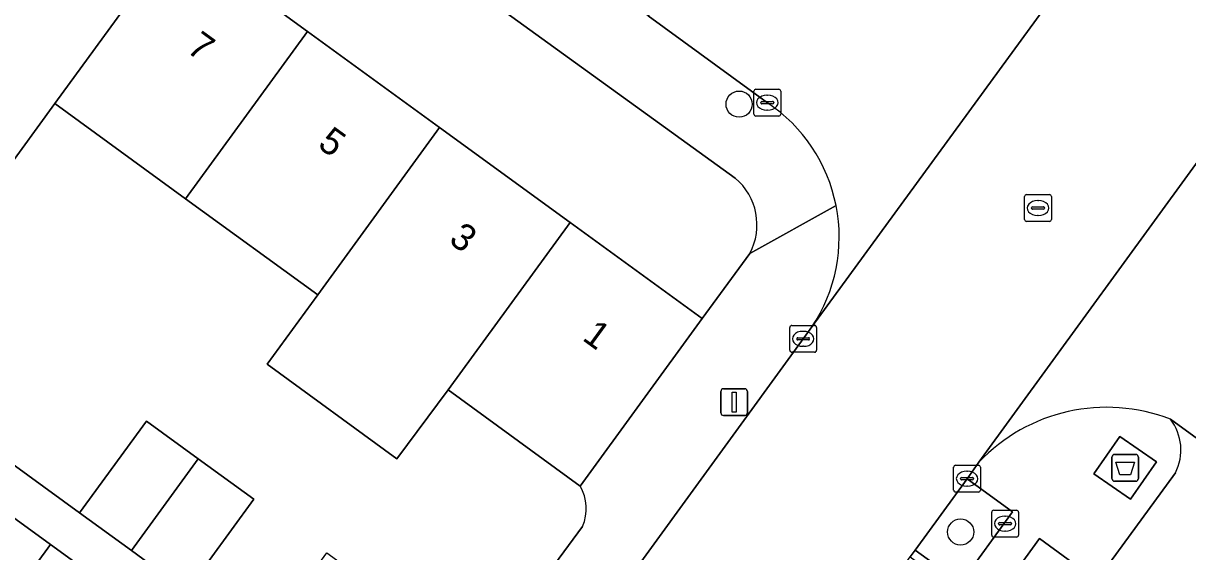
# Model space of a CAD drawing. Extents: x 159674 to 160531, y 382172 to 382904.
# Drawn here: x 160250.27 to 160293.73, y 382582.22 to 382601.94 of the extents above; entities that cross this region are included whole.
import ezdxf

# ---------------------------------------------------------------- set-up
doc = ezdxf.new("R2010")
doc.units = 0
for name, color, linetype in [('IMGEO_Afval_apart_plaats', 7, 'Continuous'), ('IMGEO_Boom', 7, 'Continuous'), ('IMGEO_Brandkraan', 7, 'Continuous'), ('IMGEO_Erf', 7, 'Continuous'), ('IMGEO_Groenvoorziening', 7, 'Continuous'), ('IMGEO_Kolk', 7, 'Continuous'), ('IMGEO_Lichtmast', 7, 'Continuous'), ('IMGEO_Muur', 7, 'Continuous'), ('IMGEO_Pand', 7, 'Continuous'), ('IMGEO_Pand_nummerreeks', 7, 'Continuous'), ('IMGEO_Parkeervlak_open', 7, 'Continuous'), ('IMGEO_Rijbaan_lokaal_gesloten', 7, 'Continuous'), ('IMGEO_Rijbaan_lokaal_open', 7, 'Continuous'), ('IMGEO_Rioolput', 7, 'Continuous'), ('IMGEO_Voetpad_gesloten', 7, 'Continuous'), ('IMGEO_Voetpad_open', 7, 'Continuous')]:
    doc.layers.add(name, color=color, linetype=linetype)

msp = doc.modelspace()

# ---------------------------------------------------------------- linework, layer by layer
at = {"layer": 'IMGEO_Afval_apart_plaats'}
for p, q in [((160290.903, 382584.947), (160290.903, 382585.747)), ((160290.903, 382585.747), (160290.903, 382584.947)), ((160291.003, 382585.847), (160291.793, 382585.847)), ((160291.793, 382585.847), (160291.003, 382585.847)), ((160291.893, 382585.747), (160291.893, 382584.947)), ((160291.893, 382584.947), (160291.893, 382585.747)), ((160291.793, 382584.847), (160291.003, 382584.847)), ((160291.003, 382584.847), (160291.793, 382584.847))]:
    msp.add_line(p, q, dxfattribs=at)
msp.add_lwpolyline([(160291.046, 382585.561), (160291.75, 382585.561), (160291.601, 382585.091), (160291.195, 382585.091), (160291.046, 382585.561)], dxfattribs=at)
for centre, start, end in [((160291.003, 382585.747), 90, 180), ((160291.003, 382585.747), 90, 180), ((160291.793, 382585.747), 0, 90), ((160291.793, 382585.747), 360, 90), ((160291.003, 382584.947), 180, 270), ((160291.003, 382584.947), 180, 270), ((160291.793, 382584.947), 270, 0), ((160291.793, 382584.947), 270, 0)]:
    msp.add_arc(centre, 0.1, start, end, dxfattribs=at)
at = {"layer": 'IMGEO_Boom'}
for centre in [(160276.99, 382598.923), (160285.257, 382582.952)]:
    msp.add_circle(centre, 0.489, dxfattribs=at)
at = {"layer": 'IMGEO_Brandkraan'}
for p, q in [((160286.416, 382582.839), (160286.416, 382583.691)), ((160286.491, 382583.765), (160287.343, 382583.765)), ((160286.904, 382583.545), (160286.929, 382583.545)), ((160287.417, 382583.691), (160287.417, 382582.839)), ((160286.675, 382583.259), (160286.675, 382583.271)), ((160287.113, 382583.222), (160286.715, 382583.222)), ((160286.718, 382583.308), (160287.116, 382583.308)), ((160287.159, 382583.271), (160287.159, 382583.259)), ((160287.343, 382582.765), (160286.491, 382582.765)), ((160286.927, 382582.985), (160286.902, 382582.985))]:
    msp.add_line(p, q, dxfattribs=at)
for points in [[(160286.416, 382582.839), (160286.416, 382583.691)], [(160286.491, 382583.765), (160287.343, 382583.765)], [(160287.417, 382583.691), (160287.417, 382582.839)], [(160287.343, 382582.765), (160286.491, 382582.765)]]:
    msp.add_lwpolyline(points, dxfattribs=at)
for centre, radius, start, end in [((160286.493, 382583.689), 0.0765, 91.552, 178.448), ((160286.493, 382583.689), 0.0765, 91.552, 178.448), ((160287.341, 382583.689), 0.0765, 1.552, 88.448), ((160287.341, 382583.689), 0.0765, 1.552, 88.448), ((160286.715, 382583.268), 0.0403, 85.8775, 175.7526), ((160286.712, 382583.258), 0.0366, 178.938, 274.7102), ((160287.116, 382583.265), 0.043, 264.8664, 352.4533), ((160287.12, 382583.27), 0.0386, 1.7309, 96.639), ((160286.493, 382582.841), 0.0765, 181.552, 268.448), ((160286.493, 382582.841), 0.0765, 181.552, 268.448), ((160287.341, 382582.841), 0.0765, 271.552, 358.448), ((160287.341, 382582.841), 0.0765, 271.552, 358.448)]:
    msp.add_arc(centre, radius, start, end, dxfattribs=at)
for centre, major_axis, ratio, start_param, end_param in [((160286.903, 382583.265), (-0.387, 0.002), 0.722429, 4.712389, 7.853982), ((160286.928, 382583.265), (-0.39, 0.002), 0.717154, 1.570796, 4.712389)]:
    msp.add_ellipse(centre, major_axis=major_axis, ratio=ratio, start_param=start_param, end_param=end_param, dxfattribs=at)
at = {"layer": 'IMGEO_Erf'}
for points in [[(160276.843, 382596.162), (160253.992, 382612.685), (160251.138, 382608.735), (160256.003, 382605.192), (160260.883, 382601.639), (160265.812, 382598.05), (160270.68, 382594.506), (160275.606, 382590.919), (160277.39, 382593.349)], [(160259.378, 382589.214), (160261.261, 382591.801), (160256.332, 382595.389), (160251.452, 382598.943), (160249.571, 382596.36), (160244.707, 382599.903), (160239.649, 382592.926), (160242.566, 382590.809), (160245.059, 382594.233), (160246.995, 382592.823), (160249.066, 382591.315), (160246.573, 382587.891), (160252.375, 382583.666), (160254.868, 382587.09), (160256.804, 382585.68), (160258.875, 382584.172), (160256.382, 382580.748), (160259.119, 382578.762), (160261.605, 382582.176), (160266.618, 382578.526), (160267.346, 382578.004), (160271.149, 382583.159)], [(160248.843, 382579.132), (160251.284, 382582.484), (160245.602, 382586.613), (160243.161, 382583.261), (160241.166, 382584.714), (160239.162, 382586.173), (160241.603, 382589.525), (160238.707, 382591.628), (160234.032, 382585.187), (160239.007, 382581.569), (160238.409, 382580.747), (160243.42, 382577.213), (160241.909, 382575.136), (160246.549, 382571.761), (160246.751, 382571.614), (160248.457, 382573.961), (160253.249, 382570.477), (160251.542, 382568.129), (160256.431, 382564.573)], [(160271.056, 382584.669), (160266.13, 382588.256), (160264.22, 382585.689), (160259.378, 382589.214)]]:
    msp.add_lwpolyline(points, dxfattribs=at)
for centre, radius, start, end in [((160275.386, 382594.419), 2.271, 331.8954, 50.1128), ((160269.604, 382583.822), 1.681, 336.7775, 30.2712)]:
    msp.add_arc(centre, radius, start, end, dxfattribs=at)
at = {"layer": 'IMGEO_Groenvoorziening'}
msp.add_lwpolyline([(160285.497, 382584.942), (160283.56, 382582.27), (160285.262, 382581.037), (160287.198, 382583.709)], close=True, dxfattribs=at)
msp.add_lwpolyline([(160340.442, 382549.369), (160334.331, 382540.968), (160330.288, 382543.909), (160320.097, 382551.321), (160305.863, 382561.673), (160309.033, 382566.031), (160311.974, 382570.074), (160312.894, 382569.405), (160313.791, 382570.579), (160311.658, 382572.109), (160310.584, 382571.385), (160308.218, 382568.127), (160290.343, 382581.143), (160288.198, 382582.705), (160286.206, 382579.962), (160290.265, 382577.019), (160290.699, 382577.618), (160299.084, 382571.539), (160288.827, 382557.394), (160278.496, 382543.145), (160268.164, 382528.897), (160257.833, 382514.648), (160249.448, 382520.727)], dxfattribs=at)
at = {"layer": 'IMGEO_Kolk'}
for p, q in [((160277.542, 382598.552), (160277.542, 382599.404)), ((160277.617, 382599.478), (160278.469, 382599.478)), ((160278.03, 382599.258), (160278.055, 382599.258)), ((160278.543, 382599.404), (160278.543, 382598.552)), ((160277.801, 382598.972), (160277.801, 382598.984)), ((160278.239, 382598.935), (160277.841, 382598.935)), ((160277.844, 382599.021), (160278.242, 382599.021)), ((160278.285, 382598.984), (160278.285, 382598.972)), ((160278.469, 382598.478), (160277.617, 382598.478)), ((160278.053, 382598.698), (160278.028, 382598.698)), ((160278.88, 382589.737), (160278.88, 382590.589)), ((160278.955, 382590.663), (160279.807, 382590.663)), ((160279.881, 382590.589), (160279.881, 382589.737)), ((160279.139, 382590.157), (160279.139, 382590.169)), ((160279.577, 382590.12), (160279.179, 382590.12)), ((160279.182, 382590.206), (160279.58, 382590.206)), ((160279.368, 382590.443), (160279.393, 382590.443)), ((160279.623, 382590.169), (160279.623, 382590.157)), ((160279.807, 382589.663), (160278.955, 382589.663)), ((160279.391, 382589.883), (160279.366, 382589.883)), ((160284.997, 382584.515), (160284.997, 382585.367)), ((160285.072, 382585.441), (160285.924, 382585.441)), ((160285.998, 382585.367), (160285.998, 382584.515)), ((160285.256, 382584.935), (160285.256, 382584.947)), ((160285.694, 382584.898), (160285.296, 382584.898)), ((160285.299, 382584.984), (160285.697, 382584.984)), ((160285.485, 382585.221), (160285.51, 382585.221)), ((160285.74, 382584.947), (160285.74, 382584.935)), ((160285.924, 382584.441), (160285.072, 382584.441)), ((160285.508, 382584.661), (160285.483, 382584.661))]:
    msp.add_line(p, q, dxfattribs=at)
for points in [[(160277.542, 382598.552), (160277.542, 382599.404)], [(160277.617, 382599.478), (160278.469, 382599.478)], [(160278.543, 382599.404), (160278.543, 382598.552)], [(160278.469, 382598.478), (160277.617, 382598.478)], [(160278.88, 382589.737), (160278.88, 382590.589)], [(160278.955, 382590.663), (160279.807, 382590.663)], [(160279.881, 382590.589), (160279.881, 382589.737)], [(160279.807, 382589.663), (160278.955, 382589.663)], [(160284.997, 382584.515), (160284.997, 382585.367)], [(160285.072, 382585.441), (160285.924, 382585.441)], [(160285.998, 382585.367), (160285.998, 382584.515)], [(160285.924, 382584.441), (160285.072, 382584.441)]]:
    msp.add_lwpolyline(points, dxfattribs=at)
for centre, radius, start, end in [((160277.619, 382599.402), 0.0765, 91.552, 178.448), ((160277.619, 382599.402), 0.0765, 91.552, 178.448), ((160278.467, 382599.402), 0.0765, 1.552, 88.448), ((160278.467, 382599.402), 0.0765, 1.552, 88.448), ((160277.841, 382598.981), 0.0403, 85.8775, 175.7526), ((160277.838, 382598.971), 0.0366, 178.938, 274.7102), ((160278.242, 382598.978), 0.043, 264.8664, 352.4533), ((160278.246, 382598.983), 0.0386, 1.7309, 96.639), ((160277.619, 382598.554), 0.0765, 181.552, 268.448), ((160277.619, 382598.554), 0.0765, 181.552, 268.448), ((160278.467, 382598.554), 0.0765, 271.552, 358.448), ((160278.467, 382598.554), 0.0765, 271.552, 358.448), ((160278.957, 382590.587), 0.0765, 91.552, 178.448), ((160278.957, 382590.587), 0.0765, 91.552, 178.448), ((160279.805, 382590.587), 0.0765, 1.552, 88.448), ((160279.805, 382590.587), 0.0765, 1.552, 88.448), ((160279.179, 382590.166), 0.0403, 85.8775, 175.7526), ((160279.176, 382590.156), 0.0366, 178.938, 274.7102), ((160279.58, 382590.163), 0.043, 264.8664, 352.4533), ((160279.584, 382590.168), 0.0386, 1.7309, 96.639), ((160278.957, 382589.739), 0.0765, 181.552, 268.448), ((160278.957, 382589.739), 0.0765, 181.552, 268.448), ((160279.805, 382589.739), 0.0765, 271.552, 358.448), ((160279.805, 382589.739), 0.0765, 271.552, 358.448), ((160285.074, 382585.365), 0.0765, 91.552, 178.448), ((160285.074, 382585.365), 0.0765, 91.552, 178.448), ((160285.922, 382585.365), 0.0765, 1.552, 88.448), ((160285.922, 382585.365), 0.0765, 1.552, 88.448), ((160285.296, 382584.944), 0.0403, 85.8775, 175.7526), ((160285.293, 382584.934), 0.0366, 178.938, 274.7102), ((160285.697, 382584.941), 0.043, 264.8664, 352.4533), ((160285.701, 382584.946), 0.0386, 1.7309, 96.639), ((160285.074, 382584.517), 0.0765, 181.552, 268.448), ((160285.074, 382584.517), 0.0765, 181.552, 268.448), ((160285.922, 382584.517), 0.0765, 271.552, 358.448), ((160285.922, 382584.517), 0.0765, 271.552, 358.448)]:
    msp.add_arc(centre, radius, start, end, dxfattribs=at)
for centre, major_axis, ratio, start_param, end_param in [((160278.029, 382598.978), (-0.387, 0.002), 0.722429, 4.712389, 7.853982), ((160278.054, 382598.978), (-0.39, 0.002), 0.717154, 1.570796, 4.712389), ((160279.367, 382590.163), (-0.387, 0.002), 0.722429, 4.712389, 7.853982), ((160279.392, 382590.163), (-0.39, 0.002), 0.717154, 1.570796, 4.712389), ((160285.484, 382584.941), (-0.387, 0.002), 0.722429, 4.712389, 7.853982), ((160285.509, 382584.941), (-0.39, 0.002), 0.717154, 1.570796, 4.712389)]:
    msp.add_ellipse(centre, major_axis=major_axis, ratio=ratio, start_param=start_param, end_param=end_param, dxfattribs=at)
at = {"layer": 'IMGEO_Lichtmast'}
for p, q in [((160276.307, 382587.4), (160276.307, 382588.2)), ((160276.307, 382588.2), (160276.307, 382587.4)), ((160276.407, 382588.3), (160277.197, 382588.3)), ((160277.197, 382588.3), (160276.407, 382588.3)), ((160277.297, 382588.2), (160277.297, 382587.4)), ((160277.297, 382587.4), (160277.297, 382588.2)), ((160277.197, 382587.3), (160276.407, 382587.3)), ((160276.407, 382587.3), (160277.197, 382587.3))]:
    msp.add_line(p, q, dxfattribs=at)
msp.add_lwpolyline([(160276.727, 382588.175), (160276.877, 382588.175), (160276.877, 382587.425), (160276.727, 382587.425), (160276.727, 382588.175)], dxfattribs=at)
for centre, start, end in [((160276.407, 382588.2), 90, 180), ((160276.407, 382588.2), 90, 180), ((160277.197, 382588.2), 0, 90), ((160277.197, 382588.2), 360, 90), ((160276.407, 382587.4), 180, 270), ((160276.407, 382587.4), 180, 270), ((160277.197, 382587.4), 270, 0), ((160277.197, 382587.4), 270, 0)]:
    msp.add_arc(centre, 0.1, start, end, dxfattribs=at)
at = {"layer": 'IMGEO_Muur'}
msp.add_arc((160269.604, 382583.822), 1.681, 336.7775, 30.2712, dxfattribs=at)
at = {"layer": 'IMGEO_Pand'}
for points in [[(160256.003, 382605.192), (160251.138, 382608.735), (160246.587, 382602.485), (160244.707, 382599.903), (160249.571, 382596.36), (160251.452, 382598.943)], [(160256.003, 382605.192), (160251.452, 382598.943), (160256.332, 382595.389), (160260.883, 382601.639)], [(160261.261, 382591.801), (160265.812, 382598.05), (160260.883, 382601.639), (160256.332, 382595.389)], [(160261.261, 382591.801), (160259.378, 382589.214), (160264.22, 382585.689), (160266.13, 382588.256), (160270.68, 382594.506), (160265.812, 382598.05)], [(160266.13, 382588.256), (160271.056, 382584.669), (160275.606, 382590.919), (160270.68, 382594.506)], [(160254.311, 382582.256), (160256.804, 382585.68), (160254.868, 382587.09), (160252.375, 382583.666)], [(160254.311, 382582.256), (160256.382, 382580.748), (160258.875, 382584.172), (160256.804, 382585.68)], [(160253.286, 382581.026), (160251.284, 382582.484), (160248.843, 382579.132), (160250.847, 382577.673)]]:
    msp.add_lwpolyline(points, close=True, dxfattribs=at)
at = {"layer": 'IMGEO_Parkeervlak_open'}
for points in [[(160313.617, 382572.218), (160293.086, 382587.159)], [(160293.272, 382585.165), (160290.343, 382581.143), (160308.218, 382568.127), (160310.584, 382571.385), (160311.658, 382572.109)]]:
    msp.add_lwpolyline(points, dxfattribs=at)
msp.add_arc((160291.629, 382586.017), 1.851, 332.5782, 38.0801, dxfattribs=at)
at = {"layer": 'IMGEO_Rijbaan_lokaal_gesloten'}
for points in [[(160315.311, 382639.622), (160304.717, 382625.008), (160302.639, 382622.143), (160290.62, 382605.563), (160279.709, 382590.612), (160279.414, 382590.208), (160269.482, 382576.534), (160263.507, 382568.309), (160253.466, 382554.485), (160253.079, 382553.951), (160242.339, 382539.119), (160232.376, 382525.365), (160226.58, 382517.362), (160218.061, 382505.6), (160216.652, 382503.655), (160216.208, 382503.063), (160216.121, 382502.946), (160214.024, 382500), (160205.773, 382488.409), (160195.682, 382474.429), (160187.988, 382463.77), (160179.328, 382451.773), (160168.227, 382436.541)], [(160249.155, 382534.809), (160256.944, 382545.554), (160259.145, 382548.59), (160262.654, 382553.43), (160263.762, 382554.959), (160267.262, 382559.788), (160279.748, 382577.012), (160283.38, 382582.021), (160283.56, 382582.27), (160285.497, 382584.942), (160285.942, 382585.556), (160295.155, 382598.231), (160297.594, 382601.591), (160301.944, 382607.584), (160305.116, 382611.954), (160310.216, 382618.98), (160313.661, 382623.726), (160314.718, 382625.182), (160318.081, 382629.815)]]:
    msp.add_lwpolyline(points, dxfattribs=at)
at = {"layer": 'IMGEO_Rijbaan_lokaal_open'}
for points in [[(160281.775, 382604.747), (160277.634, 382607.759), (160273.601, 382602.215), (160278.047, 382598.976)], [(160279.709, 382590.612), (160290.62, 382605.563)], [(160295.155, 382598.231), (160285.942, 382585.556)], [(160293.086, 382587.159), (160313.617, 382572.218), (160341.99, 382551.571), (160344.044, 382554.45), (160343.467, 382554.933)]]:
    msp.add_lwpolyline(points, dxfattribs=at)
for centre, radius, start, end in [((160274.69, 382593.961), 6.035, 11.2477, 56.2013), ((160274.693, 382593.962), 6.032, 326.2646, 11.2421), ((160290.704, 382581.053), 6.554, 68.6909, 136.6027)]:
    msp.add_arc(centre, radius, start, end, dxfattribs=at)
at = {"layer": 'IMGEO_Rioolput'}
for p, q in [((160287.645, 382594.62), (160287.645, 382595.472)), ((160287.72, 382595.546), (160288.572, 382595.546)), ((160288.133, 382595.326), (160288.158, 382595.326)), ((160288.646, 382595.472), (160288.646, 382594.62)), ((160287.904, 382595.04), (160287.904, 382595.052)), ((160288.342, 382595.003), (160287.944, 382595.003)), ((160287.947, 382595.089), (160288.345, 382595.089)), ((160288.388, 382595.052), (160288.388, 382595.04)), ((160288.572, 382594.546), (160287.72, 382594.546)), ((160288.156, 382594.766), (160288.131, 382594.766))]:
    msp.add_line(p, q, dxfattribs=at)
for points in [[(160287.645, 382594.62), (160287.645, 382595.472)], [(160287.72, 382595.546), (160288.572, 382595.546)], [(160288.646, 382595.472), (160288.646, 382594.62)], [(160288.572, 382594.546), (160287.72, 382594.546)]]:
    msp.add_lwpolyline(points, dxfattribs=at)
for centre, radius, start, end in [((160287.722, 382595.47), 0.0765, 91.552, 178.448), ((160287.722, 382595.47), 0.0765, 91.552, 178.448), ((160288.57, 382595.47), 0.0765, 1.552, 88.448), ((160288.57, 382595.47), 0.0765, 1.552, 88.448), ((160287.944, 382595.049), 0.0403, 85.8775, 175.7526), ((160287.941, 382595.039), 0.0366, 178.938, 274.7102), ((160288.345, 382595.046), 0.043, 264.8664, 352.4533), ((160288.349, 382595.051), 0.0386, 1.7309, 96.639), ((160287.722, 382594.622), 0.0765, 181.552, 268.448), ((160287.722, 382594.622), 0.0765, 181.552, 268.448), ((160288.57, 382594.622), 0.0765, 271.552, 358.448), ((160288.57, 382594.622), 0.0765, 271.552, 358.448)]:
    msp.add_arc(centre, radius, start, end, dxfattribs=at)
for centre, major_axis, ratio, start_param, end_param in [((160288.132, 382595.046), (-0.387, 0.002), 0.722429, 4.712389, 7.853982), ((160288.157, 382595.046), (-0.39, 0.002), 0.717154, 1.570796, 4.712389)]:
    msp.add_ellipse(centre, major_axis=major_axis, ratio=ratio, start_param=start_param, end_param=end_param, dxfattribs=at)
at = {"layer": 'IMGEO_Voetpad_gesloten'}
msp.add_lwpolyline([(160292.567, 382585.568), (160291.201, 382586.52), (160290.229, 382585.125), (160291.595, 382584.173)], close=True, dxfattribs=at)
at = {"layer": 'IMGEO_Voetpad_open'}
for points in [[(160195.833, 382656.371), (160252.294, 382615.273), (160251.643, 382614.384), (160253.992, 382612.685), (160276.843, 382596.162)], [(160278.047, 382598.976), (160273.601, 382602.215), (160271.282, 382603.905), (160233.343, 382631.547), (160228.441, 382635.114), (160226.048, 382636.856)], [(160280.609, 382595.138), (160277.39, 382593.349), (160275.606, 382590.919), (160271.056, 382584.669)], [(160277.39, 382593.349), (160280.609, 382595.138)], [(160279.414, 382590.208), (160279.709, 382590.612)], [(160271.149, 382583.159), (160267.346, 382578.004), (160269.482, 382576.534), (160279.414, 382590.208)], [(160285.942, 382585.556), (160285.497, 382584.942), (160287.198, 382583.709), (160285.262, 382581.037), (160283.56, 382582.27), (160283.38, 382582.021), (160286.206, 382579.962), (160288.198, 382582.705), (160290.343, 382581.143), (160293.272, 382585.165)]]:
    msp.add_lwpolyline(points, dxfattribs=at)
for points in [[(160246.573, 382587.891), (160244.502, 382589.399), (160242.566, 382590.809), (160239.649, 382592.926), (160238.707, 382591.628), (160241.603, 382589.525), (160243.605, 382588.067), (160245.602, 382586.613), (160251.284, 382582.484), (160253.286, 382581.026), (160255.283, 382579.572), (160258.248, 382577.474), (160263.256, 382573.828), (160264.132, 382575.112), (160259.119, 382578.762), (160256.382, 382580.748), (160254.311, 382582.256), (160252.375, 382583.666)], [(160290.229, 382585.125), (160291.201, 382586.52), (160292.567, 382585.568), (160291.595, 382584.173)]]:
    msp.add_lwpolyline(points, close=True, dxfattribs=at)
for centre, radius, start, end in [((160274.69, 382593.961), 6.035, 11.2477, 56.2013), ((160275.386, 382594.419), 2.271, 331.8954, 50.1128), ((160274.693, 382593.962), 6.032, 326.2646, 11.2421), ((160290.704, 382581.053), 6.554, 68.6909, 136.6027), ((160291.629, 382586.017), 1.851, 332.5782, 38.0801), ((160269.604, 382583.822), 1.681, 336.7775, 30.2712)]:
    msp.add_arc(centre, radius, start, end, dxfattribs=at)

# ---------------------------------------------------------------- texts
at = {"layer": 'IMGEO_Pand_nummerreeks'}
for s, p in [('7', (160256.324, 382600.901)), ('5', (160261.218, 382597.338)), ('3', (160266.112, 382593.774)), ('1', (160271.097, 382590.143))]:
    msp.add_text(s, height=1, rotation=323.9403, dxfattribs=at).set_placement(p)

doc.saveas('drawing.dxf')
